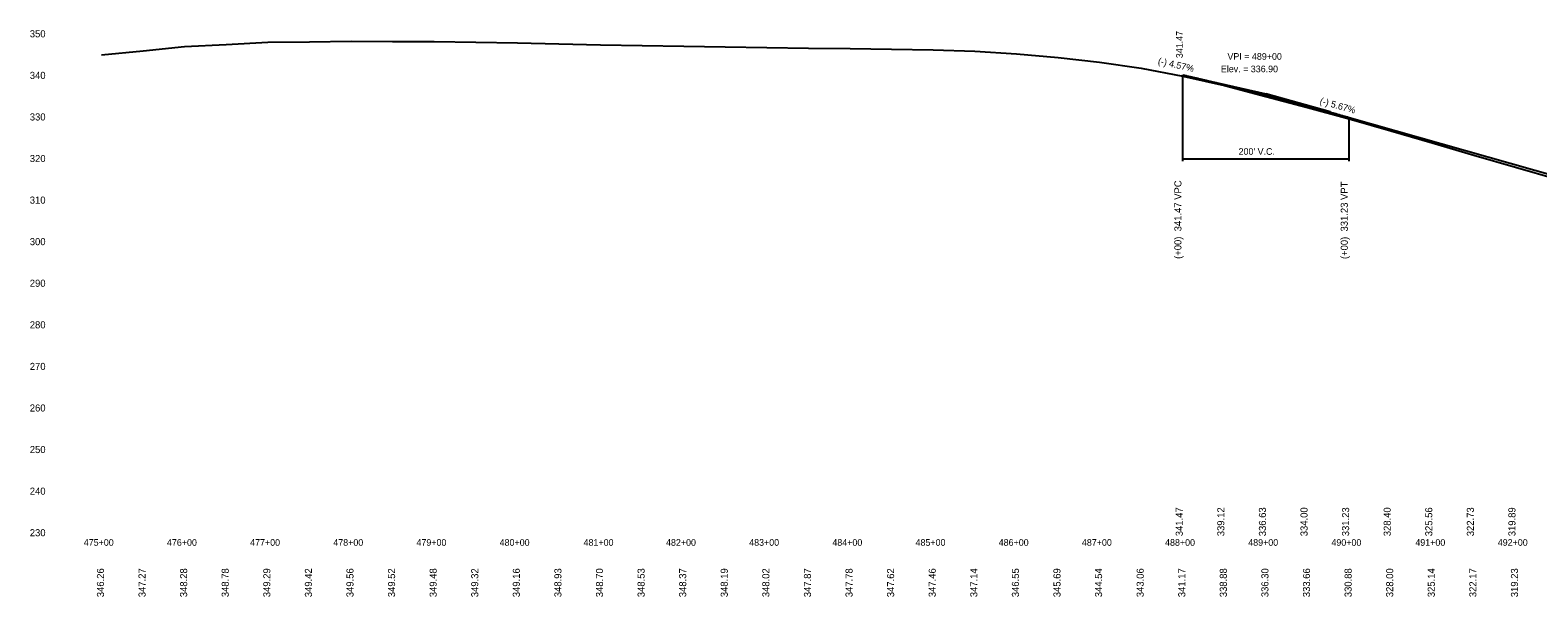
# Model space of a CAD drawing. Extents: x 1354 to 11940, y 17935 to 18885.
# Drawn here: x 1354 to 3167, y 17938 to 18620 of the extents above; entities that cross this region are included whole.
import ezdxf

# ---------------------------------------------------------------- set-up
doc = ezdxf.new("R2010")
doc.units = 0
for name, color, linetype in [('Level 40', 7, 'Continuous'), ('Level 41', 7, 'Continuous'), ('Level 42', 7, 'Continuous'), ('Level 43', 7, 'Continuous'), ('Level 45', 7, 'Continuous')]:
    doc.layers.add(name, color=color, linetype=linetype)

msp = doc.modelspace()

# ---------------------------------------------------------------- linework, layer by layer
at = {"layer": 'Level 40'}
msp.add_lwpolyline([(1439.7, 18589.8), (1489.7, 18594.9), (1539.7, 18599.9), (1589.7, 18602.4), (1639.7, 18605), (1689.7, 18605.6), (1739.7, 18606.3), (1789.7, 18606.1), (1839.7, 18605.9), (1889.7, 18605.1), (1939.7, 18604.3), (1989.7, 18603.2), (2039.7, 18602), (2089.7, 18601.2), (2139.7, 18600.4), (2189.7, 18599.5), (2239.7, 18598.6), (2289.7, 18597.9), (2339.7, 18597.4), (2389.7, 18596.6), (2439.7, 18595.8), (2489.7, 18594.2), (2539.7, 18591.3), (2589.7, 18586.9), (2639.7, 18581.2), (2689.7, 18573.8), (2739.7, 18564.3), (2789.7, 18552.9), (2839.7, 18540), (2889.7, 18526.8), (2939.7, 18512.9), (2989.7, 18498.5), (3039.7, 18484.2), (3089.7, 18469.3), (3139.7, 18454.7), (3189.7, 18440.5)], dxfattribs=at)
at = {"layer": 'Level 41'}
for p, q in [((2739.7, 18462.2), (2739.7, 18565.9)), ((2761.8, 18560.8), (2839.7, 18543)), ((2916.7, 18521.2), (2839.7, 18543)), ((2939.7, 18462.2), (2939.7, 18514.7)), ((2739.7, 18464.7), (2939.7, 18464.7))]:
    msp.add_line(p, q, dxfattribs=at)
at = {"layer": 'Level 45'}
msp.add_line((2939.7, 18514.7), (3189.7, 18443.8), dxfattribs=at)
msp.add_spline([(2739.7, 18565.9), (2743.7, 18564.9), (2747.7, 18564), (2751.7, 18563.1), (2755.7, 18562.2), (2759.7, 18561.2), (2763.7, 18560.3), (2767.7, 18559.3), (2771.7, 18558.4), (2775.7, 18557.4), (2779.7, 18556.5), (2783.7, 18555.5), (2787.7, 18554.6), (2791.7, 18553.6), (2795.7, 18552.6), (2799.7, 18551.6), (2803.7, 18550.7), (2807.7, 18549.7), (2811.7, 18548.7), (2815.7, 18547.7), (2819.7, 18546.7), (2823.7, 18545.7), (2827.7, 18544.7), (2831.7, 18543.7), (2835.7, 18542.7), (2839.7, 18541.6), (2843.7, 18540.6), (2847.7, 18539.6), (2851.7, 18538.5), (2855.7, 18537.5), (2859.7, 18536.5), (2863.7, 18535.4), (2867.7, 18534.4), (2871.7, 18533.3), (2875.7, 18532.2), (2879.7, 18531.2), (2883.7, 18530.1), (2887.7, 18529), (2891.7, 18527.9), (2895.7, 18526.9), (2899.7, 18525.8), (2903.7, 18524.7), (2907.7, 18523.6), (2911.7, 18522.5), (2915.7, 18521.4), (2919.7, 18520.3), (2923.7, 18519.2), (2927.7, 18518), (2931.7, 18516.9), (2935.7, 18515.8), (2939.7, 18514.7)], degree=3, dxfattribs=at)

# ---------------------------------------------------------------- texts
at = {"layer": 'Level 41'}
for s, height, rotation, p in [('341.47', 8, 90, (2739.7, 18585.9)), ('341.47', 8, 90, (2739.7, 18585.9)), ('(-) 4.57%', 8, 347.1289, (2709.3, 18579)), ('(-) 5.67%', 8, 344.174, (2903.8, 18531.1)), ('(+00)  341.47 VPC', 8.5, 90, (2738.1, 18344.5)), ('(+00)  331.23 VPT', 8.5, 90, (2938.1, 18344.3))]:
    msp.add_text(s, height=height, rotation=rotation, dxfattribs=at).set_placement(p)
for s, p in [('VPI = 489+00', (2793.4, 18584)), ('Elev. = 336.90', (2785.5, 18569)), ("200' V.C.", (2806.8, 18469.7))]:
    msp.add_text(s, height=8, dxfattribs=at).set_placement(p)
at = {"layer": 'Level 42'}
for s, height, p in [('350', 8.5, (1353.5, 18611)), ('340', 8.5, (1353.5, 18561)), ('330', 8.5, (1353.5, 18511)), ('330', 8.5, (1353.5, 18511)), ('320', 8.5, (1353.5, 18461)), ('320', 8.5, (1353.5, 18461)), ('310', 8.5, (1353.5, 18411)), ('310', 8.5, (1353.5, 18411)), ('300', 8.5, (1353.5, 18361)), ('300', 8.5, (1353.5, 18361)), ('290', 8.5, (1353.5, 18311)), ('290', 8.5, (1353.5, 18311)), ('280', 8.5, (1353.5, 18261)), ('280', 8.5, (1353.5, 18261)), ('270', 8.5, (1353.5, 18211)), ('270', 8.5, (1353.5, 18211)), ('260', 8.5, (1353.5, 18161)), ('260', 8.5, (1353.5, 18161)), ('250', 8.5, (1353.5, 18111)), ('250', 8.5, (1353.5, 18111)), ('240', 8.5, (1353.5, 18061)), ('240', 8.5, (1353.5, 18061)), ('230', 8.5, (1353.5, 18011)), ('230', 8.5, (1353.5, 18011)), ('475+00', 8, (1418.4, 17999.5)), ('476+00', 8, (1518.4, 17999.5)), ('477+00', 8, (1618.4, 17999.5)), ('478+00', 8, (1718.4, 17999.5)), ('479+00', 8, (1818.4, 17999.5)), ('480+00', 8, (1918.4, 17999.5)), ('481+00', 8, (2019.3, 17999.5)), ('482+00', 8, (2118.4, 17999.5)), ('483+00', 8, (2218.4, 17999.5)), ('484+00', 8, (2318.4, 17999.5)), ('485+00', 8, (2418.4, 17999.5)), ('486+00', 8, (2518.4, 17999.5)), ('487+00', 8, (2618.4, 17999.5)), ('488+00', 8, (2718.4, 17999.5)), ('489+00', 8, (2818.4, 17999.5)), ('490+00', 8, (2918.4, 17999.5)), ('491+00', 8, (3019.3, 17999.5)), ('492+00', 8, (3118.4, 17999.5))]:
    msp.add_text(s, height=height, dxfattribs=at).set_placement(p)
at = {"layer": 'Level 43'}
for s, p in [('341.47', (2739.7, 18011)), ('339.12', (2789.7, 18011)), ('336.63', (2839.7, 18011)), ('334.00', (2889.7, 18011)), ('331.23', (2939.7, 18011)), ('328.40', (2989.7, 18011)), ('325.56', (3039.7, 18011)), ('322.73', (3089.7, 18011)), ('319.89', (3139.7, 18011)), ('346.26', (1442.7, 17937.7)), ('347.27', (1492.7, 17937.7)), ('348.28', (1542.7, 17937.7)), ('348.78', (1592.7, 17937.7)), ('349.29', (1642.7, 17937.7)), ('349.42', (1692.7, 17937.7)), ('349.56', (1742.7, 17937.7)), ('349.52', (1792.7, 17937.7)), ('349.48', (1842.7, 17937.7)), ('349.32', (1892.7, 17937.7)), ('349.16', (1942.7, 17937.7)), ('348.93', (1992.7, 17937.7)), ('348.70', (2042.7, 17937.7)), ('348.53', (2092.7, 17937.7)), ('348.37', (2142.7, 17937.7)), ('348.19', (2192.7, 17937.7)), ('348.02', (2242.7, 17937.7)), ('347.87', (2292.7, 17937.7)), ('347.78', (2342.7, 17937.7)), ('347.62', (2392.7, 17937.7)), ('347.46', (2442.7, 17937.7)), ('347.14', (2492.7, 17937.7)), ('346.55', (2542.7, 17937.7)), ('345.69', (2592.7, 17937.7)), ('344.54', (2642.7, 17937.7)), ('343.06', (2692.7, 17937.7)), ('341.17', (2742.7, 17937.7)), ('338.88', (2792.7, 17937.7)), ('336.30', (2842.7, 17937.7)), ('333.66', (2892.7, 17937.7)), ('330.88', (2942.7, 17937.7)), ('328.00', (2992.7, 17937.7)), ('325.14', (3042.7, 17937.7)), ('322.17', (3092.7, 17937.7)), ('319.23', (3142.7, 17937.7))]:
    msp.add_text(s, height=8.5, rotation=90, dxfattribs=at).set_placement(p)

doc.saveas('drawing.dxf')
